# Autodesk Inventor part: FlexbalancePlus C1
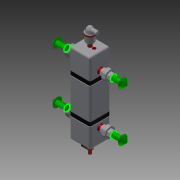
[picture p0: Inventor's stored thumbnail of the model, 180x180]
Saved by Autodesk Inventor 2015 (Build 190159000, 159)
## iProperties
allow_slope_adjustment: 0 ul
connection_type: 13 ul
flow_configuration2: 1 ul
flow_direction: 2 ul
loss_method: 0 ul
radius: 17,500 mm
description: 0:0:28377_Flexbalance Ecoplus C1
manufacturer: 0:0:Flamco Group
model: 0:0:Flexbalance
url: 0:0:http://www.flamcogroup.com
Created: 2015-09
Part Number: FlexbalancePlus C1
Material: Generic
Document SubType Name: Modeling
Designer: edwin
Density: 1 g/cm^3
Appearance: Default
Author: edwin
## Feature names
1. Revolution1
2. Sweep1
3. Extrusion2
4. Circular Pattern1
5. Revolution3
6. Extrusion3
7. Fillet1
8. Revolution2
9. Extrusion1
10. Extrusion4
11. Circular Pattern2
12. Extrusion5
13. Circular Pattern3
14. Extrusion6
15. Circular Pattern4
16. Revolution4
17. Extrusion7
18. Extrusion8
19. Circular Pattern5
20. Fillet2
21. Extrusion9
22. Fillet3
23. Extrusion10
24. Extrusion11
25. Extrusion12
26. Rectangular Pattern1
27. Revolution5
28. Extrusion13
29. Circular Pattern6
30. Extrusion14
31. Circular Pattern7
32. Extrusion15
33. Circular Pattern8
34. Extrusion16
35. Rectangular Pattern2
36. Extrusion17
37. Chamfer1
38. Extrusion18
39. Chamfer2
## Parameters: d0 = 90 deg, d1 = 0, d2 = 0, d3 = 90 deg, d4 = 35 mm, d6 = 0, d12 = 20.3349 mm, d15 = 14 mm, d16 = 0, d18 = 360 deg, d20 = 90 deg, d21 = 47.15 mm, d22 = 15 mm, d23 = 0, d24 = 1.5 mm, d27 = 15 mm, d28 = 0, d30 = 360 deg, d34 = 15 mm, d35 = 0, d37 = 360 deg, d39 = 15 mm, d40 = 0, d42 = 360 deg, d44 = 90 deg, d48 = 5.7321 mm, d49 = 0, d51 = 360 deg, d53 = 12.8 mm, d55 = 0, d56 = 1.5 mm, d57 = 15.5 mm, d65 = 0, d66 = 1 mm, d67 = 16.6 mm, d68 = 3.5 mm, d69 = 0, d71 = 9 mm, d72 = 0, d73 = 3 mm, d74 = 0, d79 = 90 deg, d84 = 0, d86 = 360 deg, d91 = 0, d93 = 360 deg, d96 = 0, d98 = 360 deg, d100 = 35 mm, d102 = 0, d105 = 276 mm, d107 = 17.2 mm, d108 = 2.3349 mm, d109 = 0, d110 = 0.5 mm, d111 = 2 mm, d112 = 45 deg, d113 = 12.5 mm, d115 = 0, d116 = 1 mm, d117 = 2 mm, d118 = 45 deg
